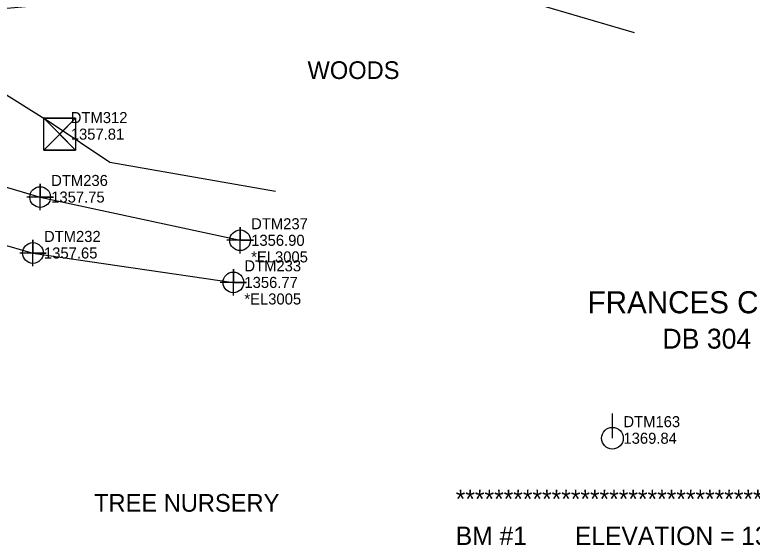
# Model space of a CAD drawing. Extents: x 1251492 to 1253015, y 859607 to 860610.
# Drawn here: x 1252086.7 to 1252253.4, y 859871.3 to 859991.3 of the extents above; entities that cross this region are included whole.
import ezdxf

# ---------------------------------------------------------------- set-up
doc = ezdxf.new("R2010")
doc.units = 0
for name, color, linetype in [('CTL Bench Mark CELL', 7, 'Continuous'), ('CTL Sheet Text', 7, 'Continuous'), ('CTL Supplemental Vertical Cogo Elevation', 7, 'Continuous'), ('CTL Supplemental Vertical Cogo Number', 7, 'Continuous'), ('Exist Property Deed Book Text', 7, 'Continuous'), ('Exist Property Owner Text', 7, 'Continuous'), ('Exist Roads Soil', 7, 'Continuous'), ('Exist Roads Soil Cogo Comment', 7, 'Continuous'), ('Exist Roads Soil Cogo Elevation', 7, 'Continuous'), ('Exist Roads Soil Cogo Number', 7, 'Continuous'), ('Exist Roads Soil Cogo Point CELL', 7, 'Continuous'), ('Exist Utilities Power Pole CELL', 7, 'Continuous'), ('Exist Utilities Power Pole Cogo Elevation', 7, 'Continuous'), ('Exist Utilities Power Pole Cogo Number', 7, 'Continuous'), ('Exist Vegetation Woods Line', 7, 'Continuous'), ('Exist Vegetation Woods Line Text', 7, 'Continuous')]:
    doc.layers.add(name, color=color, linetype=linetype)

msp = doc.modelspace()

# ---------------------------------------------------------------- linework, layer by layer
at = {"layer": 'CTL Bench Mark CELL'}
msp.add_line((1252096.83, 859964.3), (1252096.83, 859964.3), dxfattribs=at)
msp.add_lwpolyline([(1252093.23, 859967.88), (1252100.42, 859967.88), (1252100.42, 859960.7), (1252093.23, 859960.7)], close=True, dxfattribs=at)
for points in [[(1252100.42, 859967.88), (1252093.23, 859960.7), (1252096.83, 859964.29), (1252100.42, 859960.7), (1252093.23, 859967.88)], [(1252096.83, 859964.29), (1252100.42, 859967.88), (1252093.23, 859967.88), (1252096.83, 859964.29)], [(1252096.83, 859964.29), (1252093.23, 859960.7), (1252100.42, 859960.7), (1252096.83, 859964.29)]]:
    msp.add_lwpolyline(points, dxfattribs=at)
at = {"layer": 'Exist Roads Soil'}
for points in [[(1252044.79, 859969.9), (1252064.82, 859958.22), (1252092.4, 859950.07), (1252137.62, 859940.28)], [(1252044.1, 859950.97), (1252090.77, 859937.41), (1252136.09, 859930.76)]]:
    msp.add_lwpolyline(points, dxfattribs=at)
at = {"layer": 'Exist Roads Soil Cogo Point CELL'}
for points in [[(1252092.4, 859947.07), (1252092.4, 859953.07), (1252092.4, 859950.07), (1252095.4, 859950.07), (1252089.4, 859950.07)], [(1252137.62, 859937.28), (1252137.62, 859943.28), (1252137.62, 859940.28), (1252140.62, 859940.28), (1252134.62, 859940.28)], [(1252090.77, 859934.41), (1252090.77, 859940.41), (1252090.77, 859937.41), (1252093.77, 859937.41), (1252087.77, 859937.41)], [(1252136.09, 859927.76), (1252136.09, 859933.76), (1252136.09, 859930.76), (1252139.09, 859930.76), (1252133.09, 859930.76)]]:
    msp.add_lwpolyline(points, dxfattribs=at)
for centre in [(1252092.4, 859950.07), (1252137.62, 859940.28), (1252090.77, 859937.41), (1252136.09, 859930.76)]:
    msp.add_circle(centre, 2.34, dxfattribs=at)
at = {"layer": 'Exist Utilities Power Pole CELL'}
for q in [(1252221.8, 859901.12), (1252221.8, 859895.5)]:
    msp.add_line((1252221.8, 859895.5), q, dxfattribs=at)
msp.add_circle((1252221.8, 859895.5), 2.45, dxfattribs=at)
at = {"layer": 'Exist Vegetation Woods Line'}
msp.add_lwpolyline([(1252145.64, 859951.31), (1252108.13, 859957.92), (1252094.66, 859966.91), (1252070.62, 859981.97), (1252076.43, 859992.01), (1252113.41, 859995.45), (1252148.54, 860008.13), (1252186.58, 859999.15), (1252226.74, 859987.26)], dxfattribs=at)

# ---------------------------------------------------------------- texts
at = {"layer": 'CTL Sheet Text'}
for s, p in [('****************************************', (1252186.38, 859879.69)), ("BM #1       ELEVATION = 1357.7855'", (1252186.38, 859871.35))]:
    msp.add_text(s, height=4.1667, dxfattribs=at).set_placement(p)
at = {"layer": 'CTL Supplemental Vertical Cogo Elevation'}
msp.add_text('1357.81', height=2.5, dxfattribs=at).set_placement((1252099.33, 859963.05))
at = {"layer": 'CTL Supplemental Vertical Cogo Number'}
msp.add_text('DTM312', height=2.5, dxfattribs=at).set_placement((1252099.33, 859966.8))
at = {"layer": 'Exist Property Deed Book Text'}
msp.add_text('DB 304 PG 0219', height=4.5, dxfattribs=at).set_placement((1252233.13, 859915.78))
at = {"layer": 'Exist Property Owner Text'}
msp.add_text('FRANCES CHURCH HEIRS', height=5, dxfattribs=at).set_placement((1252216.2, 859923.77))
at = {"layer": 'Exist Roads Soil Cogo Comment'}
for p in [(1252140.12, 859935.28), (1252138.59, 859925.76)]:
    msp.add_text('*EL3005', height=2.5, dxfattribs=at).set_placement(p)
at = {"layer": 'Exist Roads Soil Cogo Elevation'}
for s, p in [('1357.75', (1252094.9, 859948.82)), ('1356.90', (1252140.12, 859939.03)), ('1357.65', (1252093.27, 859936.16)), ('1356.77', (1252138.59, 859929.51))]:
    msp.add_text(s, height=2.5, dxfattribs=at).set_placement(p)
at = {"layer": 'Exist Roads Soil Cogo Number'}
for s, p in [('DTM236', (1252094.9, 859952.57)), ('DTM237', (1252140.12, 859942.78)), ('DTM232', (1252093.27, 859939.91)), ('DTM233', (1252138.59, 859933.26))]:
    msp.add_text(s, height=2.5, dxfattribs=at).set_placement(p)
at = {"layer": 'Exist Utilities Power Pole Cogo Elevation'}
msp.add_text('1369.84', height=2.5, dxfattribs=at).set_placement((1252224.3, 859894.25))
at = {"layer": 'Exist Utilities Power Pole Cogo Number'}
msp.add_text('DTM163', height=2.5, dxfattribs=at).set_placement((1252224.3, 859898))
at = {"layer": 'Exist Vegetation Woods Line Text'}
for s, p in [('WOODS', (1252152.86, 859976.78)), ('TREE NURSERY', (1252104.59, 859878.88))]:
    msp.add_text(s, height=4, dxfattribs=at).set_placement(p)

doc.saveas('drawing.dxf')
